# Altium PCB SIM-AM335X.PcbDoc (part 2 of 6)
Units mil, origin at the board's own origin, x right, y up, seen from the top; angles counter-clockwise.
Board outline 4041.51 x 2715.24 mil, 2 copper layers (Top Layer, Bottom Layer); 172 components, 190 nets, 855 pads, 317 vias.
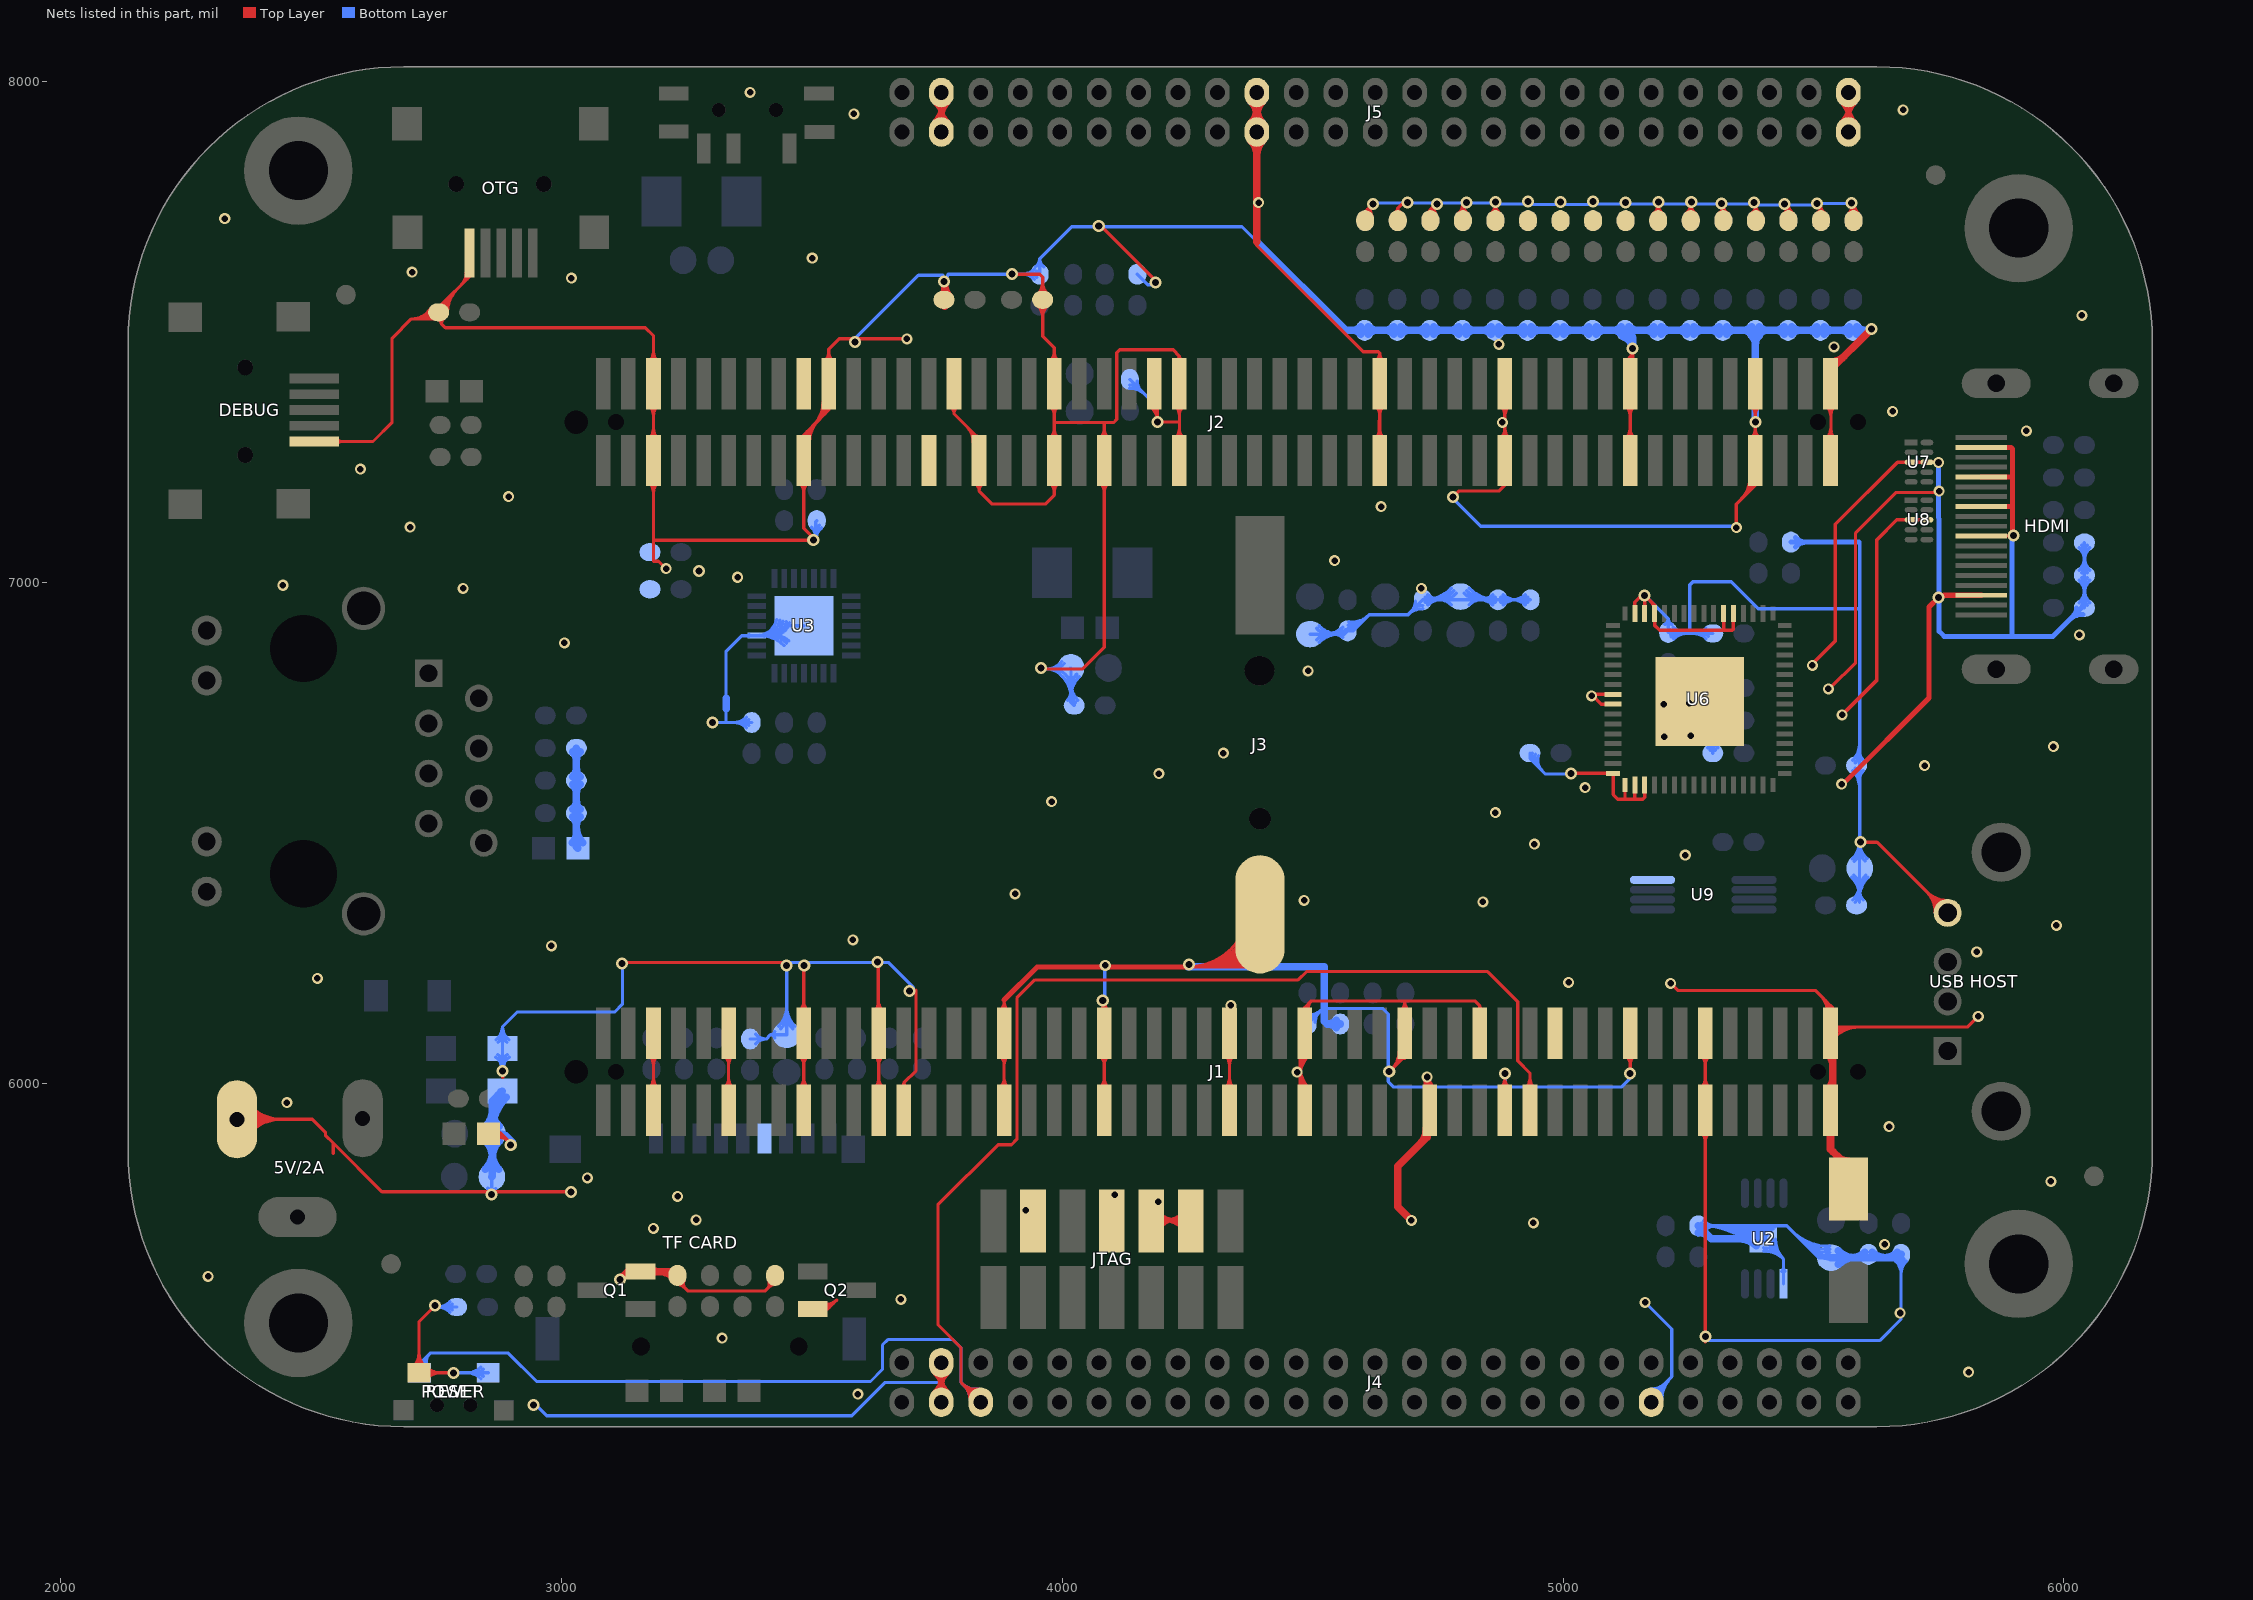
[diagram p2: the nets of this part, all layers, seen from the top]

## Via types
v1: diameter 24, hole 14, Top Layer to Bottom Layer, tented both sides, 206 vias
v2: diameter 22, hole 13, Top Layer to Bottom Layer, tented both sides, 109 vias
v3: diameter 22, hole 14, Top Layer to Bottom Layer, tented both sides, 2 vias

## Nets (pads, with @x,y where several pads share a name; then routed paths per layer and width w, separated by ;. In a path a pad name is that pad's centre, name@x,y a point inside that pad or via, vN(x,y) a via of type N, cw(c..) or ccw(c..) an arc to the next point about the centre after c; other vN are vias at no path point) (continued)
DGND: 5V/2A.3 "TF CARD.6" "USB HOST.4" C1.2 C2.2 C3.2 C4.1 C22.1 C23.2 C24.2 C25.2 C27.2 C28.2 C29.2 C30.1 C31.2 C32.2 C33.2 C34.2 C52.1 C53.2 C54.1 C55.1 C56.2 C57.2 C58.2 C59.2 C60.2 C61.2 C62.2 C63.2 C64.2 C65.2 C66.2 C67.2 C68.2 C69.2 C70.2 C71.2 C72.2 C73.2 C74.2 C75.2 C76.2 C77.2 C78.2 C79.2 C80.2 C81.2 C82.1 C83.2 CE1.2 CE2.2 CE3.2 DEBUG.5 ESD1.2 ESD2.2 ESD3.2 ESD4.2 ESD5.2 HDMI.2 HDMI.5 HDMI.8 HDMI.11 HDMI.17 J1.5 J1.6 J1.11 J1.12 J1.17 J1.18 J1.23 J1.24 J1.25 J1.33 J1.34 J1.41 J1.42 J1.51 J1.52 J1.57 J1.58 J1.66 J1.67 J1.72 J1.73 J1.84 J1.89 J1.90 J1.99 J1.100 J2.5 J2.6 J2.17 J2.20 J2.27 J2.30 J2.31 J2.37 J2.38 J2.41 J2.46 J2.47 J2.48 J2.63 J2.64 J2.73 J2.74 J2.83 J2.84 J2.93 J2.94 J2.99 J2.100 J3.2 J4.3 J4.4 J4.39 J5.3 J5.4 J5.19 J5.20 J5.49 J5.50 JTAG.4 JTAG.8 JTAG.10 JTAG.12 L1.2 LED4.2 OTG.5 POWER.2 Q1.2 Q2.2 R23.1 R24.1 R25.2 R26.2 R27.2 R28.2 R29.2 R30.2 R31.2 R32.2 R33.2 R34.2 R35.2 R36.2 R37.2 R38.2 R39.2 R40.2 R43.2 R54.2 R57.1 R59.2 R74.1 R93.1 R94.1 R96.2 RESET.2 U2.1 U2.9 U3.3 U3.29 U6.8 U6.9 U6.16 U6.17 U6.18 U6.19 U6.53 U6.54 U6.61 U6.62 U6.63 U6.65 U7.3 U7.8 U8.3 U8.8 U9.4 | length 48401.6
  Top Layer w6.5: 5V/2A.3@2352.47,5928.79 2352.47,5929 2503,5929 2529,5903 2529,5896.9 2544.45,5881.45 ; 5V/2A.3@2364.67,5916.59 cw(c2394.62,5886.64) 2394.62,5929 ; 5V/2A.3@2364.67,5940.99 ccw(c2393.61,5969.93) 2393.61,5929 ; 5V/2A.3@2369.26,5912 cw(c2410.31,5870.95) 2410.31,5929 ; 5V/2A.3@2369.26,5945.58 ccw(c2409.3,5985.62) 2409.3,5929 ; 5V/2A.3@2373.86,5907.4 cw(c2426.01,5855.25) 2426.01,5929 ; 5V/2A.3@2373.86,5950.18 ccw(c2424.99,6001.31) 2424.99,5929 ; 5V/2A.3@2378.46,5902.8 cw(c2441.7,5839.56) 2441.7,5929 ; 5V/2A.3@2378.46,5954.78 ccw(c2440.69,6017.01) 2440.69,5929 ; DEBUG.5@2506.69,7282.01 2624,7282.01 2662,7320.01 2662,7488 2700.73,7526.73 ; 2544.45,5860.55 2544.45,5881.45 ; DEBUG.5@2550.72,7277.35 cw(c2561.97,7266.09) 2561.97,7282.01 cw(c2561.97,7297.92) DEBUG.5@2550.72,7286.67 ; POWER.2@2704.38,5434.12 ccw(c2676.32,5462.18) 2716,5462.18 ccw(c2755.68,5462.18) POWER.2@2727.62,5434.12 ; POWER.2@2708.97,5429.53 ccw(c2692.01,5446.49) 2716,5446.49 ccw(c2739.99,5446.49) POWER.2@2723.03,5429.53 ; 2712.63,7526.73 ccw(c2712.63,7565.26) ESD1.2@2745.06,7544.46 ; 2724.52,7526.73 ccw(c2724.52,7557.63) ESD1.2@2750.53,7540.95 ; POWER.2@2725.98,5415.47 cw(c2742.94,5398.51) 2742.94,5422.5 cw(c2742.94,5446.49) POWER.2@2725.98,5429.53 ; POWER.2@2730.57,5410.88 cw(c2758.63,5382.82) 2758.63,5422.5 cw(c2758.63,5462.18) POWER.2@2730.57,5434.12 ; 2736.41,7526.73 ccw(c2736.41,7550) ESD1.2@2756,7537.43 ; ESD1.2@2739.59,7547.97 cw(c2700.73,7572.89) 2700.73,7526.73 ; v1(2748,5557) 2716,5525 POWER.2@2716,5422.5 v1(2785,5422.5) ; ESD1.2@2753.8,7525.86 cw(c2751.13,7516.86) 2760.51,7516.86 cw(c2773.75,7516.86) ESD1.2@2766.3,7527.81 ; ESD1.2@2759.75,7540 cw(c2794.12,7540) 2769.82,7564.31 ; ESD1.2@2766.25,7540 cw(c2816.32,7540) 2780.91,7575.4 ; ESD1.2@2772.75,7540 cw(c2838.51,7540) 2792.01,7586.5 ; 2800.49,7594.97 ccw(c2776.51,7618.95) OTG.5@2810.42,7618.95 ; 2811.58,7606.07 ccw(c2798.71,7618.95) OTG.5@2816.92,7618.95 ; OTG.5@2817.01,7658.32 2817.01,7611.5 2760.51,7555 ESD1.2@2760.51,7526.73 ; LED4.2@2853.57,5906.6 cw(c2860,5876.59) 2881.71,5898.29 ; LED4.2@2854.49,5900 2880,5900 ; LED4.2@2854.94,5900.24 cw(c2862.99,5862.67) 2890.16,5889.84 ; LED4.2@2856.3,5893.89 cw(c2865.97,5848.75) v1@2898.61,5881.39 ; LED4.2@2873.6,5895.07 cw(c2880,5893.38) 2880,5900 ; LED4.2@2873.6,5904.93 ccw(c2880,5906.62) 2880,5900 ; 2883,6012 v1(2883,6025) ; v1@2903,5877 2880,5900 ; v1(3019,5784) 2641.9,5784 2544.45,5881.45 ; v1@3130,6242 3450,6242.25 v1@3452,6242.25 ; J1.5@3176,5991.62 ccw(c3156.68,6010.94) 3184,6010.94 ccw(c3211.32,6010.94) J1.5@3192,5991.62 ; J1.6@3176,6055.93 cw(c3156.68,6036.61) 3184,6036.61 cw(c3211.32,6036.61) J1.6@3192,6055.93 ; J2.5@3176,7199.38 cw(c3156.68,7180.06) 3184,7180.06 cw(c3211.32,7180.06) J2.5@3192,7199.38 ; J2.5@3176,7288.62 ccw(c3156.68,7307.94) 3184,7307.94 ccw(c3211.32,7307.94) J2.5@3192,7288.62 ; J2.6@3176,7352.93 cw(c3156.68,7333.61) 3184,7333.61 cw(c3211.32,7333.61) J2.6@3192,7352.93 ; J2.6@3176,7442.16 ccw(c3156.68,7461.48) 3184,7461.48 ccw(c3211.32,7461.48) J2.6@3192,7442.16 ; J1.5@3184,5947 J1.6@3184,6100.54 ; v2(3209,7028) 3194,7043 3184,7043 3184,7085 ; R23.1@3231.8,5599.25 cw(c3231.8,5582.48) 3243.66,5594.34 ; R23.1@3231.8,5617 3231.8,5606.2 3252,5586 3407,5586 3426.8,5605.8 R24.1@3426.8,5617 ; R23.1@3239.24,5610.42 ccw(c3250.32,5605.08) 3241.62,5596.38 ; R23.1@3245.09,5607.6 ccw(c3259.06,5600.87) 3248.1,5589.9 ; J1.11@3326,5991.62 ccw(c3306.68,6010.94) 3334,6010.94 ccw(c3361.32,6010.94) J1.11@3342,5991.62 ; J1.12@3326,6055.93 cw(c3306.68,6036.61) 3334,6036.61 cw(c3361.32,6036.61) J1.12@3342,6055.93 ; J1.11@3334,5947 J1.12@3334,6100.54 ; 3411.1,5590.1 ccw(c3400.77,5600.43) R24.1@3413.72,5607.18 ; 3415.62,5594.62 cw(c3426.8,5583.43) R24.1@3426.8,5599.25 ; 3417.36,5596.36 ccw(c3409,5604.72) R24.1@3419.49,5610.19 ; J1.17@3476,5991.62 ccw(c3456.68,6010.94) 3484,6010.94 ccw(c3511.32,6010.94) J1.17@3492,5991.62 ; J1.18@3476,6055.93 cw(c3456.68,6036.61) 3484,6036.61 cw(c3511.32,6036.61) J1.18@3492,6055.93 ; J1.18@3476,6145.16 ccw(c3456.68,6164.48) 3484,6164.48 ccw(c3511.32,6164.48) J1.18@3492,6145.16 ; J2.17@3476,7199.38 cw(c3456.68,7180.06) 3484,7180.06 cw(c3511.32,7180.06) J2.17@3492,7199.38 ; J2.17@3482.32,7280.61 cw(c3512.98,7280.61) 3491.3,7302.3 ; J1.17@3484,5947 J1.18@3484,6100.54 v1@3484,6234 ; J2.17@3488.82,7280.61 cw(c3535.18,7280.61) 3502.4,7313.4 ; J2.17@3495.32,7280.61 cw(c3557.37,7280.61) 3513.49,7324.49 ; Q2.2@3502,5550.2 3532.2,5550.2 ; 3503.42,7314.42 ccw(c3456.9,7360.93) J2.20@3522.68,7360.93 ; 3514.51,7325.51 ccw(c3479.1,7360.93) J2.20@3529.18,7360.93 ; Q2.2@3515.6,5549.73 ccw(c3522.55,5567.4) 3535.97,5553.97 ; Q2.2@3517.98,5555.78 ccw(c3526.51,5577.46) 3542.99,5560.99 ; Q2.2@3520.35,5561.83 ccw(c3530.47,5587.53) 3550,5568 3532.2,5550.2 ; 3525.61,7336.61 ccw(c3501.29,7360.93) J2.20@3535.68,7360.93 ; J2.20@3526,7442.16 ccw(c3506.68,7461.48) 3534,7461.48 ccw(c3561.32,7461.48) J2.20@3542,7442.16 ; Q2.2@3527.83,5546.87 cw(c3532.2,5545.66) 3532.2,5550.2 ; Q2.2@3527.83,5553.52 ccw(c3532.2,5554.73) 3532.2,5550.2 ; J2.20@3530.28,7350.24 cw(c3528.45,7345) 3534,7345 ; J2.20@3537.72,7350.24 ccw(c3539.55,7345) 3534,7345 ; J1.23@3626,5991.62 ccw(c3606.68,6010.94) 3634,6010.94 ccw(c3661.32,6010.94) J1.23@3642,5991.62 ; J1.24@3626,6055.93 cw(c3606.68,6036.61) 3634,6036.61 cw(c3661.32,6036.61) J1.24@3642,6055.93 ; J1.24@3626,6145.16 ccw(c3609.09,6162.07) 3633,6162.07 ; 3633,6166.89 ccw(c3663.74,6166.89) J1.24@3642,6145.16 ; v1@3633,6243 3633,6101.54 J1.24@3634,6100.54 J1.23@3634,5947 ; J1.25@3679.08,5993.81 ccw(c3675.29,6001.65) 3684,6001.65 ; J1.25@3684,5947 3684,6001.65 ; J1.25@3688.92,5993.81 cw(c3692.71,6001.65) 3684,6001.65 ; v2(3690,7487) 3555,7487 3534,7466 J2.20@3534,7397.54 3534,7345 ; 3708.32,6186.44 3708.32,6025.96 3684,6001.65 ; J5.3@3743.07,7919.44 ccw(c3698.22,7961) J5.4@3759.33,7963.33 ; J4.3@3743.5,5384.02 ccw(c3707.05,5420.48) 3758.61,5420.48 ccw(c3810.16,5420.48) J4.3@3773.71,5384.02 ; J4.4@3743.5,5422.72 cw(c3707.05,5386.26) 3758.61,5386.26 cw(c3810.16,5386.26) J4.4@3773.71,5422.72 ; J5.4@3744.22,7958.15 cw(c3708.75,7919.87) J5.3@3760.91,7921.85 ; J5.3@3747.84,7915.02 ccw(c3714.5,7945.92) 3759.92,7947.65 ; J4.3@3748.1,5379.43 ccw(c3722.74,5404.79) 3758.61,5404.79 ccw(c3794.47,5404.79) J4.3@3769.11,5379.43 ; J4.4@3748.1,5427.31 cw(c3722.74,5401.95) 3758.61,5401.95 cw(c3794.47,5401.95) J4.4@3769.11,5427.31 ; J5.4@3748.64,7962.92 cw(c3723.83,7936.14) 3760.31,7937.53 ; J5.3@3752.61,7910.6 ccw(c3730.77,7930.83) 3760.52,7931.97 ; J4.3@3758.61,5364 J4.4@3758.61,5442.74 ; J5.4@3758.74,7978.74 J5.3@3761.74,7900 ; J5.4@3759.84,7949.77 ccw(c3801.78,7951.37) J5.3@3773.26,7920.59 ; 3760.28,7938.44 cw(c3795.48,7939.78) J5.4@3769.64,7963.72 ; 3760.44,7934.09 ccw(c3786.69,7935.09) J5.3@3768.84,7915.82 ; J5.3@3760.87,7922.76 cw(c3811.76,7924.7) J5.4@3774.41,7959.3 ; J2.30@3776.82,7352.18 cw(c3764.36,7337) 3784,7337 ; J2.30@3784,7397.54 3784,7337 ; J2.30@3791.18,7352.18 ccw(c3803.64,7337) 3784,7337 ; 3810.17,7310.83 cw(c3779.95,7280.61) J2.31@3822.68,7280.61 ; 3821.26,7299.74 cw(c3802.14,7280.61) J2.31@3829.18,7280.61 ; 3825.58,7295.42 ccw(c3834,7303.84) J2.31@3834,7291.93 ; J2.31@3826.69,7198.74 cw(c3813.39,7183) 3834,7183 ; J2.31@3841.31,7198.74 ccw(c3854.61,7183) 3834,7183 ; J1.33@3876,5991.62 ccw(c3856.68,6010.94) 3884,6010.94 ccw(c3911.32,6010.94) J1.33@3892,5991.62 ; J1.34@3876,6055.93 cw(c3856.68,6036.61) 3884,6036.61 cw(c3911.32,6036.61) J1.34@3892,6055.93 ; J1.34@3876,6145.16 ccw(c3856.68,6164.48) 3884,6164.48 ccw(c3911.32,6164.48) J1.34@3892,6145.16 ; J1.33@3884,5947 J1.34@3884,6100.54 3884,6167 ; v1(3900,7616) 3955,7616 3961,7610 ESD2.2@3961,7565 3961,7492 3984,7469 J2.38@3984,7397.54 3984,7320 ; ESD2.2@3950.57,7554.57 cw(c3925.39,7529.39) 3961,7529.39 cw(c3996.61,7529.39) ESD2.2@3971.43,7554.57 ; ESD2.2@3950.57,7575.43 ccw(c3925.39,7600.61) 3961,7600.61 ccw(c3996.61,7600.61) ESD2.2@3971.43,7575.43 ; ESD2.2@3955.17,7559.17 cw(c3941.08,7545.08) 3961,7545.08 cw(c3980.92,7545.08) ESD2.2@3966.83,7559.17 ; ESD2.2@3955.17,7570.83 ccw(c3941.08,7584.92) 3961,7584.92 ccw(c3980.92,7584.92) ESD2.2@3966.83,7570.83 ; v1@3969,6828 4041,6828 4084,6871 J2.41@4084,7244 4084,7318 4082,7320 ; J2.37@3976,7199.38 cw(c3956.68,7180.06) 3984,7180.06 cw(c4011.32,7180.06) J2.37@3992,7199.38 ; J2.37@3976,7288.62 ccw(c3956.68,7307.94) 3984,7307.94 ccw(c4011.32,7307.94) J2.37@3992,7288.62 ; J2.38@3976,7352.93 cw(c3956.68,7333.61) 3984,7333.61 cw(c4011.32,7333.61) J2.38@3992,7352.93 ; J2.38@3976,7442.16 ccw(c3956.68,7461.48) 3984,7461.48 ccw(c4011.32,7461.48) J2.38@3992,7442.16 ; J1.41@4076,5991.62 ccw(c4056.68,6010.94) 4084,6010.94 ccw(c4111.32,6010.94) J1.41@4092,5991.62 ; J1.42@4076,6055.93 cw(c4056.68,6036.61) 4084,6036.61 cw(c4111.32,6036.61) J1.42@4092,6055.93 ; J2.41@4076,7199.38 cw(c4056.68,7180.06) 4084,7180.06 cw(c4111.32,7180.06) J2.41@4092,7199.38 ; J2.41@4076,7288.62 ccw(c4056.68,7307.94) 4084,7307.94 ccw(c4111.32,7307.94) J2.41@4092,7288.62 ; J1.42@4076.17,6145.33 ccw(c4056.39,6166) 4085,6166 4085,6101.54 J1.42@4084,6100.54 J1.41@4084,5947 ; v1@4081,7709 4188,7602 v1@4188,7595 ; v1@4085,6162.07 ccw(c4108.91,6162.07) J1.42@4092,6145.16 ; J2.46@4176.36,7352.58 cw(c4146.98,7320.48) v1@4190.5,7320.48 ; J2.46@4180.75,7357.38 cw(c4160.49,7335.23) 4190.5,7335.23 ; J2.46@4184,7397.54 4190.5,7391.04 v1(4190.5,7321) 4190.73,7320.77 4234,7320.77 ; JTAG.10@4189,5728 4189.14,5727.86 4228.7,5727.86 ; JTAG.10@4189.2,5737.2 ccw(c4211.76,5759.76) 4211.76,5727.86 ; JTAG.10@4190.32,5716.04 cw(c4215.08,5696) 4215.08,5727.86 ; JTAG.10@4193.8,5741.8 ccw(c4227.45,5775.45) 4227.45,5727.86 ; JTAG.10@4195.37,5711.95 cw(c4228.7,5684.99) 4228.7,5727.86 ; JTAG.10@4197.94,5727.86 cw(c4197.94,5667.09) JTAG.12@4240.9,5710.06 ; 4207.6,5727.86 ccw(c4207.6,5774.96) JTAG.12@4240.9,5741.66 ; 4213.63,5727.86 cw(c4213.63,5682.79) JTAG.12@4245.5,5714.66 ; 4223.29,5727.86 ccw(c4223.29,5759.27) JTAG.12@4245.5,5737.06 ; J2.47@4226,7288.62 ccw(c4206.68,7307.94) 4234,7307.94 ccw(c4261.32,7307.94) J2.47@4242,7288.62 ; J2.48@4226,7352.93 cw(c4206.68,7333.61) 4234,7333.61 cw(c4261.32,7333.61) J2.48@4242,7352.93 ; J2.48@4228.87,7444.24 ccw(c4224.61,7452.61) 4234,7452.61 ; 4229.32,5727.86 cw(c4229.32,5698.48) JTAG.12@4250.1,5719.25 ; J2.47@4234,7244 4234,7320.77 ; JTAG.12@4234.58,5722.75 ccw(c4228.7,5721.92) 4228.7,5727.86 ; JTAG.12@4235.46,5732.76 cw(c4228.7,5734.96) 4228.7,5727.86 ; J2.48@4239.13,7444.24 cw(c4243.39,7452.61) 4234,7452.61 ; v1@4262.44,6233 ccw(c4262.44,6347.77) J3.2@4361.08,6289.11 ; 4273.86,6233 ccw(c4273.86,6340.98) J3.2@4366.67,6285.79 ; 4285.29,6233 ccw(c4285.29,6334.18) J3.2@4372.26,6282.46 ; 4296.72,6233 ccw(c4296.72,6327.38) J3.2@4377.84,6279.14 ; 4308.15,6233 ccw(c4308.15,6320.59) J3.2@4383.43,6275.82 ; 4319.58,6233 ccw(c4319.58,6313.79) J3.2@4389.02,6272.5 ; J1.51@4326,5991.62 ccw(c4306.68,6010.94) 4334,6010.94 ccw(c4361.32,6010.94) J1.51@4342,5991.62 ; J1.52@4326,6055.93 cw(c4306.68,6036.61) 4334,6036.61 cw(c4361.32,6036.61) J1.52@4342,6055.93 ; 4331,6233 ccw(c4331,6306.99) J3.2@4394.6,6269.17 ; J1.51@4334,5947 J1.52@4334,6100.54 ; 4342.43,6233 ccw(c4342.43,6300.2) J3.2@4400.19,6265.85 ; 4353.86,6233 ccw(c4353.86,6293.4) J3.2@4405.78,6262.53 ; J3.2@4355.5,6292.43 cw(c4251.01,6354.57) 4251.01,6233 4395,6233 J3.2@4395,6337.83 ; 4388.66,7681.34 4388.66,7673.34 4601,7461 4631.27,7461 4634,7458.27 ; J1.57@4475,5946.75 4475,6100.3 4484,6152 4497,6165 ; 4475,6001.27 ccw(c4501.66,6001.27) J1.57@4482.81,5982.42 ; v2@4475,6014.89 cw(c4533.04,6014.89) J1.58@4492,6055.93 ; v2@4475,6016.97 ccw(c4517.35,6016.97) J1.57@4487.41,5987.02 ; v2@4475,6030.58 cw(c4517.35,6030.58) J1.58@4487.41,6060.52 ; 4475,6032.66 ccw(c4533.04,6032.66) J1.57@4492,5991.62 ; 4475,6046.27 cw(c4501.66,6046.27) J1.58@4482.81,6065.12 ; J1.58@4482.53,6136.34 cw(c4494.6,6143.06) 4484.83,6152.83 ; J1.58@4488.21,6139.5 cw(c4502.41,6147.42) 4490.91,6158.91 ; J1.58@4493.89,6142.67 cw(c4510.23,6151.77) 4497,6165 ; C58.2@4605,7723 4605,7741 4622,7758 ccw(c4637.27,7742.73) C58.2@4618.1,7732.79 ; C58.2@4606.55,7726.81 cw(c4620.73,7734.15) 4609.44,7745.44 ; C58.2@4612.32,7729.8 cw(c4629,7738.44) v1@4615.72,7751.72 ; J2.64@4626,7352.93 cw(c4606.68,7333.61) 4634,7333.61 cw(c4661.32,7333.61) J2.64@4642,7352.93 ; J2.64@4626.77,7442.86 ccw(c4613.97,7458.27) 4634,7458.27 ; 4633,7305.52 cw(c4609.09,7305.52) 4626,7288.62 ccw(c4606.68,7307.94) 4634,7307.94 ccw(c4661.32,7307.94) 4642,7288.62 cw(c4663.74,7310.35) 4633,7310.35 ; 4633,7324 4633,7215 J2.63@4634,7214 ; J2.63@4634,7244 J2.64@4634,7397.54 4634,7458.27 ; J2.64@4641.23,7442.86 cw(c4654.03,7458.27) 4634,7458.27 ; v1@4657,6024 v1(4653,6024) J1.66@4684,6055 ; v1@4658.37,6029.37 ccw(c4623.8,6063.93) J1.66@4672.68,6063.93 ; C59.2@4664.4,7739.65 ccw(c4660.97,7748) 4670,7748 ; 4669.46,6040.46 ccw(c4646,6063.93) J1.66@4679.18,6063.93 ; C59.2@4670,7723 4670,7748 ; C59.2@4675.6,7739.65 cw(c4679.03,7748) 4670,7748 ; J1.66@4676.1,6145.26 ccw(c4657.83,6164) 4684,6164 ; v1@4680,7758 4670,7748 ; J1.66@4683.76,6050 4683,6050 4684,6051 J1.66@4684,6055 ; J1.66@4691.9,6145.26 cw(c4710.17,6164) 4684,6164 ; C60.2@4731.34,7740.29 ccw(c4730.14,7745) 4735,7745 ; C60.2@4735,7723 4735,7745 ; C60.2@4736.38,7727.08 cw(c4748.6,7736.65) 4737.62,7747.62 ; C60.2@4738.66,7740.29 cw(c4739.86,7745) 4735,7745 ; C60.2@4741.49,7731.09 cw(c4754.41,7741.21) v1@4742.81,7752.81 ; C60.2@4746.61,7735.09 cw(c4760.23,7745.76) 4748,7758 4735,7745 ; v1(4780,7171) 4792,7183 4872,7183 4884,7195 J2.73@4884,7244 ; C61.2@4790.99,7737.68 ccw(c4776.87,7756) v1@4800,7756 ; C61.2@4800,7723 v1@4800,7756 ; C61.2@4809.01,7737.68 cw(c4823.13,7756) v1@4800,7756 ; J1.72@4829.18,6147.4 ccw(c4825.6,6155) 4834,6155 ; J1.72@4834,6100.54 4834,6155 ; J1.72@4838.82,6147.4 cw(c4842.4,6155) 4834,6155 ; C62.2@4855.99,7737.68 ccw(c4841.87,7756) v1@4865,7756 ; C62.2@4865,7723 v1@4865,7756 ; C62.2@4874.01,7737.68 cw(c4888.13,7756) v1@4865,7756 ; J1.73@4876,5991.62 ccw(c4856.68,6010.94) 4884,6010.94 ccw(c4911.32,6010.94) J1.73@4892,5991.62 ; J1.73@4884,5947 v1(4884,6020) ; v1@5016,6619.61 U6.16@5100,6619.61 5100,6577 5109.3,6567.7 5142.31,6567.7 ; v2@5056.93,6777.07 5076.54,6757.46 U6.9@5100,6757.46 ; v2@5057,6777.15 U6.8@5100,6777.15 ; 5123.62,6569.78 U6.17@5123.62,6595.99 ; J1.84@5126,6055.93 cw(c5106.68,6036.61) 5134,6036.61 cw(c5161.32,6036.61) J1.84@5142,6055.93 ; v1(5134,6020) J1.84@5134,6100.54 ; U6.18@5143.31,6595.99 5143.31,6568.7 5142.31,6567.7 ; U6.19@5163,6595.99 5163,6571.77 5158.93,6567.7 5142.31,6567.7 ; C67.2@5181.31,7737.92 ccw(c5168.87,7755) v1@5190,7755 ; C67.2@5190,7723 v1@5190,7755 ; v1@5191,7756 v1@5190,7755 ; C67.2@5198.69,7737.92 cw(c5211.13,7755) v1@5190,7755 ; v2(5215,6200) 5229,6186 5504,6186 5539,6151 J1.100@5539,6113.13 ; C68.2@5245.99,7737.68 ccw(c5231.87,7756) v1@5255,7756 ; C68.2@5255,7723 v1@5255,7756 ; C68.2@5264.01,7737.68 cw(c5278.13,7756) v1@5255,7756 ; J1.89@5276,5902.38 cw(c5256.68,5883.06) 5284,5883.06 cw(c5311.32,5883.06) J1.89@5292,5902.38 ; J1.89@5276,5991.62 ccw(c5256.68,6010.94) 5284,6010.94 ccw(c5311.32,6010.94) J1.89@5292,5991.62 ; J1.90@5276,6055.93 cw(c5256.68,6036.61) 5284,6036.61 cw(c5311.32,6036.61) J1.90@5292,6055.93 ; v1@5284,5484 J1.89@5284,5944 ; J1.89@5284,5947 J1.90@5284,6100.54 ; C69.2@5312.03,7738.41 ccw(c5302.66,7753) v1@5320,7753 ; v1(5316,7757) v1@5320,7753 ; C69.2@5320,7723 v1@5320,7753 ; C69.2@5327.97,7738.41 cw(c5337.34,7753) v1@5320,7753 ; J2.93@5376,7288.62 ccw(c5356.68,7307.94) 5384,7307.94 ccw(c5411.32,7307.94) J2.93@5392,7288.62 ; J2.94@5376,7352.93 cw(c5356.68,7333.61) 5384,7333.61 cw(c5411.32,7333.61) J2.94@5392,7352.93 ; C70.2@5377.03,7738.41 ccw(c5367.66,7753) v1@5385,7753 ; v1@5381,7757 v1@5385,7753 ; J2.93@5384,7244 J2.94@5384,7397.54 ; C70.2@5385,7723 v1@5385,7753 ; C70.2@5392.97,7738.41 cw(c5402.34,7753) v1@5385,7753 ; C71.2@5440.99,7737.68 ccw(c5426.87,7756) v1@5450,7756 ; C71.2@5450,7723 v1@5450,7756 ; C71.2@5459.01,7737.68 cw(c5473.13,7756) v1@5450,7756 ; C72.2@5508.34,7739.16 ccw(c5502.85,7750) v1@5515,7750 ; 5512.45,6177.55 cw(c5472.07,6137.16) J1.100@5529.18,6137.16 ; C72.2@5515,7723 v1@5515,7750 ; C72.2@5521.66,7739.16 cw(c5527.15,7750) v1@5515,7750 ; 5523.55,6166.45 cw(c5494.26,6137.16) J1.100@5535.68,6137.16 ; J1.99@5526,5902.38 cw(c5494.61,5870.99) 5539,5870.99 ; J1.99@5526,5991.62 ccw(c5494.61,6023.01) 5539,6023.01 ; J1.100@5526,6055.93 cw(c5494.61,6024.54) 5539,6024.54 ; J2.99@5526,7288.62 ccw(c5504.26,7310.35) 5535,7310.35 ; J2.100@5526,7352.93 cw(c5504.26,7331.19) 5535,7331.19 ; J1.100@5528.21,6106.33 cw(c5544.63,6089.91) J1.100@5544.63,6113.13 ; J1.99@5530.59,5906.98 cw(c5510.3,5886.69) 5539,5886.69 ; J1.99@5530.59,5987.02 ccw(c5510.3,6007.31) 5539,6007.31 ; J1.100@5530.59,6060.52 cw(c5510.3,6040.23) 5539,6040.23 ; J1.100@5532.81,6101.73 cw(c5560.32,6074.22) 5560.32,6113.13 ; J2.100@5534,7397.54 5534,7397 5535,7397 J2.99@5535,7200 ; 5534.65,6155.35 cw(c5516.45,6137.16) J1.100@5542.18,6137.16 ; v2@5534.94,6790.94 5584,6840 5584,7099.56 5664.53,7180.09 5748.27,7180.09 v2(5750.93,7182.75) ; 5535,7305.52 ccw(c5558.91,7305.52) J2.99@5542,7288.62 ; 5535,7336.02 cw(c5558.91,7336.02) J2.100@5542,7352.93 ; J1.100@5537.41,6097.14 cw(c5576.01,6058.53) 5576.01,6113.13 ; 5539,5864 J1.99@5539,5947 ; 5539,5895.14 cw(c5549.25,5895.14) J1.99@5542,5902.38 ; J1.99@5539,5952 J1.100@5539,6113.13 ; 5539,5998.86 ccw(c5549.25,5998.86) J1.99@5542,5991.62 ; 5539,6048.68 cw(c5549.25,6048.68) J1.100@5542,6055.93 ; J1.100@5542,6092.54 cw(c5591.71,6042.84) 5591.71,6113.13 ; J5.49@5554.66,7920.02 ccw(c5518.21,7956.48) 5569.76,7956.48 ccw(c5621.32,7956.48) J5.49@5584.87,7920.02 ; J5.50@5554.66,7958.72 cw(c5518.21,7922.26) 5569.76,7922.26 cw(c5621.32,7922.26) J5.50@5584.87,7958.72 ; J5.49@5559.26,7915.43 ccw(c5533.9,7940.79) 5569.76,7940.79 ccw(c5605.63,7940.79) J5.49@5580.27,7915.43 ; J5.50@5559.26,7963.31 cw(c5533.9,7937.95) 5569.76,7937.95 cw(c5605.63,7937.95) J5.50@5580.27,7963.31 ; C73.2@5569.57,7736.43 ccw(c5544.39,7761.61) 5580,7761.61 ccw(c5615.61,7761.61) C73.2@5590.43,7736.43 ; J5.49@5569.76,7900 J5.50@5569.76,7978.74 ; C73.2@5574.17,7731.83 ccw(c5560.08,7745.92) 5580,7745.92 ccw(c5599.92,7745.92) C73.2@5585.83,7731.83 ; C73.2@5580,7723 v1@5580,7763 ; v1(5594,6482) 5627,6482 5768,6341 ; 5743.3,6341 ccw(c5683.66,6341) 5725.83,6383.17 ccw(c5768,6425.34) 5768,6365.7 ; 5749.8,6341 ccw(c5705.85,6341) 5736.93,6372.07 ccw(c5768,6403.15) 5768,6359.2 ; 5756.3,6341 ccw(c5728.04,6341) 5748.02,6360.98 ccw(c5768,6380.96) 5768,6352.7 ; v2(5829,6134.13) 5808,6113.13 J1.100@5539,6113.13 ; HDMI.11@5835,7093.15 v1@5896.15,7093.15 ; 2700.73,7526.73 ESD1.2@2760.51,7526.73 ; ESD1.2@2760.51,7526.73 2760.51,7517 2768.51,7509 3168,7509 3184,7493 J2.6@3184,7397.54 J2.5@3184,7244 3184,7085 ; 3184,7085 3508,7085 3484,7109 J2.17@3484,7244 3484,7295 3534,7345 ; 3784,7337 3834,7287 J2.31@3834,7244 3834,7183 ; 3834,7183 3860,7157 3966,7157 3984,7175 J2.37@3984,7244 3984,7320 ; 3984,7320 4082,7320 ; 4082,7320 4103,7320 4109,7326 4109,7459 4115,7465 4221.62,7465 4234,7452.62 ; 4234,7320.77 J2.48@4234,7397.54 4234,7452.62 ; 4497,6165 4685,6165 ; J1.66@4684,6055 J1.66@4684,6100.54 4684,6164 ; 4684,6164 4685,6165 ; 4685,6165 4824,6165 4834,6155
  Top Layer w7: J2.73@4876.17,7288.44 ccw(c4857.28,7307.33) 4884,7307.33 ccw(c4910.72,7307.33) J2.73@4891.83,7288.44 ; J2.74@4876.17,7353.1 cw(c4857.28,7334.21) 4884,7334.21 cw(c4910.72,7334.21) J2.74@4891.83,7353.1 ; J2.73@4884,7244 J2.74@4884,7397.54 ; J2.83@5126.17,7288.44 ccw(c5107.28,7307.33) 5134,7307.33 ccw(c5160.72,7307.33) J2.83@5141.83,7288.44 ; J2.84@5126.17,7353.1 cw(c5107.28,7334.21) 5134,7334.21 cw(c5160.72,7334.21) J2.84@5141.83,7353.1 ; J2.84@5127,7442.73 ccw(c5106.4,7468) v1(5139,7468) 5139,7402.54 J2.84@5134,7397.54 J2.83@5134,7244 ; J2.84@5131.43,7437.31 ccw(c5118.42,7453.25) 5139,7453.25 ; 5139,7448.81 ccw(c5148.65,7448.81) J2.84@5141.83,7441.98 ; U6.63@5143.31,6938.62 5143.31,6961.31 5157,6975 v1(5163,6975) ; U6.62@5163,6938.62 v1(5163,6975) ; 5176.63,6961.38 cw(c5165.6,6950.35) U6.61@5181.2,6950.35 ; U6.54@5320.55,6938.62 5320.55,6905 ; U6.53@5340.24,6938.62 5340.24,6907.19 5338.05,6905 5320.55,6905 ; v2(5346,7110) 5346,7157 5384,7195 J2.93@5384,7244 ; 5356.35,7167.35 ccw(c5316.31,7207.39) J2.93@5372.93,7207.39 ; 5368.3,7179.3 ccw(c5340.21,7207.39) J2.93@5379.93,7207.39 ; 5380.25,7191.25 ccw(c5364.11,7207.39) J2.93@5386.93,7207.39 ; v2@5503,6843 5543.69,6883.69 5543.69,7116.43 5667.89,7240.63 U7.3@5695,7240.63 U7.8@5726.5,7240.63 v3@5749.63,7240.63 ; v2(5557,6736) 5626.75,6805.75 5626.75,7085.74 5666.64,7125.63 U8.3@5695,7125.63 U8.8@5726.5,7125.63 ; v1(5163,6975) 5182.7,6955.31 U6.61@5182.7,6938.62 5182.7,6915.3 5193,6905 5320.55,6905
  Top Layer w10: 3884,6167 3950,6233 v1@4251,6233 ; v2@5551.57,6599.43 5560.43,6599.43 5730.75,6769.75 5730.75,6951.75 v1(5750,6971) ; v1@5761.04,6975.04 HDMI.17@5835,6975.04 ; HDMI.8@5835,7152.2 5895.57,7152.2 5897.68,7150.09 ; HDMI.5@5835,7211.26 5895.42,7211.26 5897.68,7209 ; HDMI.2@5835,7270.32 5894.32,7270.32 5897.68,7266.95 5897.68,7209 ; v1@5896.15,7093.15 5896.15,7101.62 5897.68,7103.15 5897.68,7150.09 ; 5897.68,7150.09 5897.68,7209
  Top Layer w15: v1(3117,5609) 3132.8,5624.8 Q1.2@3158,5624.8 3224,5624.8 R23.1@3231.8,5617 ; Q1.2@3177.61,5618.97 cw(c3191.69,5604.89) 3191.69,5624.8 cw(c3191.69,5644.72) Q1.2@3177.61,5630.64 ; 3194.86,5624.8 cw(c3194.86,5583.05) R23.1@3224.38,5612.58 ; ESD3.2@3759.58,7572.42 ccw(c3744.07,7587.94) 3766,7587.94 ; ESD3.2@3766,7552 v1@3766,7601 ; v1@3766,7592.76 ccw(c3794.76,7592.76) ESD3.2@3774.42,7572.42 ; J5.19@4376.57,7882.98 cw(c4347.36,7853.78) 4388.66,7853.78 cw(c4429.96,7853.78) J5.19@4400.76,7882.98 ; J5.19@4376.57,7917.02 ccw(c4347.36,7946.22) 4388.66,7946.22 ccw(c4429.96,7946.22) J5.19@4400.76,7917.02 ; J5.20@4376.57,7961.72 cw(c4347.36,7932.52) 4388.66,7932.52 cw(c4429.96,7932.52) J5.20@4400.76,7961.72 ; 4388.66,7681.34 J5.19@4388.66,7900 J5.20@4388.66,7978.74 ; v2(4697,5727) 4670,5754 4670,5835 4728.5,5893.5 v2(4728.5,6013.18) ccw(c4762.51,6013.18) J1.67@4738.91,5988.7 ; 4713.89,5878.89 ccw(c4682.38,5910.39) J1.67@4726.93,5910.39 ; 4728.5,5892.63 cw(c4740.26,5892.63) J1.67@4736.35,5903.72 ; J1.99@5529,5905.39 cw(c5516.94,5893.32) 5534,5893.32 cw(c5551.06,5893.32) J1.99@5539,5905.39 ; J1.99@5529,5988.61 ccw(c5505.48,6012.14) 5538.75,6012.14 ; J1.100@5529,6058.93 cw(c5505.48,6035.41) 5538.75,6035.41 ; J1.100@5534,6100.54 5538.75,6095.8 5538.75,5951.75 J1.99@5534,5947 5534,5869 5539,5864 CE3.2@5570,5833 ; J2.100@5534,7397.54 5534,7425 v1@5614,7505 ; J2.100@5534,7441.23 ccw(c5534,7480.4) 5561.7,7452.7 ; 5545.78,5857.22 cw(c5520.18,5831.63) CE3.2@5554.16,5819.16 ; 5549.15,5853.85 ccw(c5570,5874.71) CE3.2@5570,5845.22
  Bottom Layer w6.5: v1(2748,5557) 2751,5554 R43.2@2791,5554 ; R43.2@2777.57,5543.57 ccw(c2752.39,5518.39) 2752.39,5554 ccw(c2752.39,5589.61) R43.2@2777.57,5564.43 ; R43.2@2782.17,5548.17 ccw(c2768.08,5534.08) 2768.08,5554 ccw(c2768.08,5573.92) R43.2@2782.17,5559.83 ; v1(2785,5422.5) RESET.2@2854,5422.5 ; RESET.2@2839.43,5410.88 ccw(c2811.37,5382.82) 2811.37,5422.5 ccw(c2811.37,5462.18) RESET.2@2839.43,5434.12 ; RESET.2@2844.02,5415.47 ccw(c2827.06,5398.51) 2827.06,5422.5 ccw(c2827.06,5446.49) RESET.2@2844.02,5429.53 ; C2.2@2852.92,5790.89 cw(c2848.21,5779) v1(2861,5779) ; C1.2@2861.1,5900.87 cw(c2875.01,5877.38) 2894.32,5896.68 ; C2.2@2861.5,5814 2861,5813.5 v1(2861,5779) ; C1.2@2862.5,5900 2891,5900 2903,5888 v1@2903,5877 ; C1.2@2864.41,5895.27 cw(c2879.42,5869.94) 2900.24,5890.76 ; C1.2@2867.72,5889.68 cw(c2883.82,5862.51) v1@2906.16,5884.84 ; CE1.2@2869.14,6052.84 cw(c2847.86,6025.5) v1@2882.5,6025.5 ; C2.2@2869.2,5790.56 ccw(c2873.25,5779) v1(2861,5779) ; CE1.2@2869.45,6087.4 ccw(c2849.88,6113.5) 2882.5,6113.5 ; CE1.2@2873.13,6057.97 cw(c2858.21,6038.8) 2882.5,6038.8 cw(c2906.79,6038.8) CE1.2@2891.87,6057.97 ; CE1.2@2873.35,6082.2 ccw(c2859.63,6100.5) 2882.5,6100.5 ccw(c2905.37,6100.5) CE1.2@2891.65,6082.2 ; v1(2883,6025) v1@2882.5,6025.5 ; CE1.2@2895.55,6087.4 cw(c2915.12,6113.5) 2882.5,6113.5 ; CE1.2@2895.86,6052.84 ccw(c2917.14,6025.5) v1@2882.5,6025.5 ; v1(2944,5358) 2950,5358 2971,5337 3580,5337 3646.46,5403.46 3758.61,5403.46 ; v1@3122,6236 3122,6158 3107,6143 2912,6143 2882.5,6113.5 ; v1(3302,6721) 3329,6721 ; 3329,6748 3329,6721 ; 3329,6769 3329,6863.37 3360,6894.37 U3.3@3390,6894.37 ; R54.2@3369.57,6710.57 ccw(c3344.39,6685.39) 3344.39,6721 ccw(c3344.39,6756.61) R54.2@3369.57,6731.43 ; R54.2@3374.17,6715.17 ccw(c3360.08,6701.08) 3360.08,6721 ccw(c3360.08,6740.92) R54.2@3374.17,6726.83 ; U3.3@3375.33,6892.49 ccw(c3370.79,6887.96) 3370.79,6894.37 ccw(c3370.79,6900.78) U3.3@3375.33,6896.25 ; C31.2@3377,6089 3409,6089 ; R54.2@3380,6721 3329,6721 ; C31.2@3388.22,6079.42 cw(c3409,6061.67) 3409,6089 ; C31.2@3388.22,6098.58 ccw(c3409,6116.33) 3409,6089 ; U3.3@3397.19,6894.37 cw(c3397.19,6826.72) U3.29@3445.03,6874.56 ; U3.3@3398.14,6894.37 ccw(c3398.14,6933.6) U3.29@3436.4,6924.92 ; U3.3@3404.67,6892.49 cw(c3409.21,6887.96) 3409.21,6894.37 cw(c3409.21,6900.78) U3.3@3404.67,6896.25 ; U3.3@3406.28,6894.37 ccw(c3406.28,6931.76) U3.29@3442.74,6923.49 ; 3412.88,6894.37 cw(c3412.88,6842.41) U3.29@3449.62,6879.15 ; 3414.42,6894.37 ccw(c3414.42,6929.91) U3.29@3449.08,6922.05 ; 3422.56,6894.37 ccw(c3422.56,6928.06) U3.29@3455.42,6920.61 ; C30.1@3426.17,6091.03 ccw(c3417.56,6088.54) 3417.5,6097.5 ; C30.1@3426.19,6104.05 cw(c3417.44,6106.63) 3417.5,6097.5 ; U3.29@3428.58,6894.37 cw(c3428.58,6858.1) U3.29@3454.22,6883.75 ; U3.29@3430.07,6926.36 cw(c3390,6935.45) U3.3@3390,6894.37 ; C30.1@3433.56,6113.94 ccw(c3393.87,6153.63) 3450,6153.63 ccw(c3506.13,6153.63) C30.1@3466.44,6113.94 ; C30.1@3438.16,6109.34 ccw(c3409.56,6137.94) 3450,6137.94 ccw(c3490.44,6137.94) C30.1@3461.84,6109.34 ; C30.1@3450,6097.5 C30.1@3450,6097.73 ; v1(3450,6236) C30.1@3450,6097.73 ; v1@3451.12,6234.88 3458.25,6242 v1@3625.75,6242 ; U3.29@3484.49,6914.02 3446.65,6914.02 3427,6894.37 U3.3@3390,6894.37 ; C24.2@3499.57,7110.57 cw(c3479.22,7090.22) v1@3508,7090.22 ; v1@3508,7084.95 cw(c3540.43,7084.95) C24.2@3519.51,7109.73 ; v1@3508,7085 3508,7122 C24.2@3510,7124 ; 3508,7098.94 cw(c3528.62,7098.94) C24.2@3515.32,7114.7 ; v1@3586,7487 3713,7614 3762,7614 ; v1@3640.25,6242 3652.76,6242 v1@3702.76,6192 ; J4.3@3749.06,5388.03 ccw(c3741.36,5403.46) 3758.61,5403.46 ; J4.3@3758.61,5364 3758.61,5403.46 ; v1@3766,7595 3772,7616 v1(3900,7616) ESD5.2@3955,7616 3955,7647 ; J4.3@3768.15,5388.03 cw(c3775.86,5403.46) 3758.61,5403.46 ; ESD5.2@3944.57,7605.57 ccw(c3919.39,7580.39) 3919.39,7616 ccw(c3919.39,7651.61) ESD5.2@3944.57,7626.43 ; ESD5.2@3946.66,7631.16 ccw(c3935.8,7647) 3955,7647 ; ESD5.2@3949.17,7610.17 ccw(c3935.08,7596.08) 3935.08,7616 ccw(c3935.08,7635.92) ESD5.2@3949.17,7621.83 ; ESD5.2@3963.34,7631.16 cw(c3974.2,7647) 3955,7647 ; 3982.28,6828 ccw(c3982.28,6855.84) C4.1@4004.27,6838.77 ; 3982.86,6828 cw(c3982.86,6799.7) C4.1@4004.62,6817.79 ; C4.1@3999.13,6842.76 cw(c3969,6866.14) v1@3969,6828 ; C4.1@3999.62,6813.64 ccw(c3969,6788.18) v1@3969,6828 ; C4.1@4017.5,6809 C4.1@4017.5,6830 4015.5,6828 v1@3969,6828 ; v1@4085,6166 4085,6227 v2@4086,6228 ; R57.1@4135,7388.25 cw(c4135,7345.4) 4165.3,7375.7 ; R57.1@4135,7394.75 cw(c4135,7367.59) 4154.2,7386.8 ; R57.1@4135,7406 4190.5,7350.5 v1(4190.5,7321) ; R57.1@4149.75,7403 ccw(c4178.12,7403) 4158.06,7382.94 ; ESD4.2@4150,7616 4171,7595 v1@4188,7595 ; 4389,7681 4359,7711 4019,7711 3955,7647 ; R74.1@4490,6119 4521,6150 4523,6150 4640,6150 4651,6139 4651,6004 4662,5993 4885,5993 ; R74.1@4490,6130.25 ccw(c4490,6157.41) 4509.2,6138.2 ; R74.1@4490,6136.75 ccw(c4490,6179.6) 4520.3,6149.3 ; R74.1@4504.75,6122 cw(c4533.12,6122) 4513.06,6142.06 ; C56.2@4570,6904 4581,6904 4613,6936 ; C56.2@4570.2,6908.74 ccw(c4573.56,6937.46) 4594.01,6917.01 ; C56.2@4570.96,6915.19 ccw(c4575.55,6954.46) 4603.51,6926.51 ; C56.2@4571.71,6921.65 ccw(c4577.54,6971.46) 4613,6936 ; v1@4622,7758 v1@4865,7758 ; 4689.7,6935.7 cw(c4720,6905.4) C57.2@4720,6948.25 ; 4696.94,6942.94 ccw(c4676.88,6963) C57.2@4705.25,6963 ; 4700.8,6946.8 cw(c4720,6927.59) C57.2@4720,6954.75 ; C57.2@4720,6966 4690,6936 4613,6936 ; v1@4865,7756 v1@4930,7756 ; v1(4884,6020) 4885,6019 4885,5993 ; v1@4930,7755 v1@5058,7755 ; C74.2@4934,6660 4934,6649 4965,6618 v1@5016,6618 ; C74.2@4938.66,6659.44 ccw(c4956.74,6653.28) 4943.23,6639.77 ; C74.2@4944.81,6657.34 ccw(c4967.76,6649.53) 4950.62,6632.38 ; C74.2@4950.96,6655.25 ccw(c4978.77,6645.77) 4958,6625 ; v1@5060,7756 5369,7756 ; v1(5134,6020) 5134,6011 5116,5993 4885,5993 ; v2(5164,5563) 5216.58,5510.42 5217,5510 5217,5415 5189,5387 5175.93,5387 J4.39@5175.93,5364 ; J4.39@5175.93,5383.78 ccw(c5175.93,5407.55) 5192.74,5390.74 ; J4.39@5175.93,5390.28 ccw(c5175.93,5429.74) 5203.84,5401.84 ; J4.39@5184.29,5368.92 cw(c5216.55,5368.92) 5193.74,5391.74 ; J4.39@5190.79,5368.92 cw(c5238.74,5368.92) 5204.83,5402.83 ; J4.39@5197.29,5368.92 cw(c5260.94,5368.92) 5215.93,5413.93 ; C79.2@5215.83,6892.17 cw(c5231.98,6876.02) 5231.98,6898.85 ; C79.2@5216,6898.85 C78.2@5299,6898.85 ; C79.2@5220.43,6887.57 cw(c5247.67,6860.33) 5247.67,6898.85 ; C79.2@5220.43,6908.43 ccw(c5243.55,6931.55) 5243.55,6898.85 ; R59.2@5270,5716 5447,5716 5510.5,5652.5 C25.2@5535,5652.5 ; R59.2@5275.83,5710.17 cw(c5289.92,5696.08) 5289.92,5716 cw(c5289.92,5735.92) R59.2@5275.83,5721.83 ; R59.2@5278.69,5716 cw(c5278.69,5568.69) U2.9@5382.85,5672.85 ; R59.2@5280.43,5705.57 cw(c5305.61,5680.39) 5305.61,5716 cw(c5305.61,5751.61) R59.2@5280.43,5726.43 ; v1@5284,5487 5632,5487 5675,5530 C22.1@5675,5659 ; C78.2@5285.57,6888.42 ccw(c5260.39,6863.24) 5260.39,6898.85 ccw(c5260.39,6934.46) C78.2@5285.57,6909.28 ; C78.2@5290.17,6893.02 ccw(c5276.08,6878.94) 5276.08,6898.85 ccw(c5276.08,6918.77) C78.2@5290.17,6904.69 ; 5294.38,5716 cw(c5294.38,5584.38) U2.9@5387.45,5677.45 ; 5310.07,5716 cw(c5310.07,5600.07) U2.9@5392.05,5682.05 ; 5325.76,5716 cw(c5325.76,5615.76) U2.9@5396.64,5686.64 ; 5336,7002 5390,6948 ; 5341.46,5716 cw(c5341.46,5631.46) U2.9@5401.24,5691.24 ; 5357.15,5716 cw(c5357.15,5647.15) U2.9@5405.83,5695.83 ; U2.9@5372.84,5716 cw(c5372.84,5662.84) U2.9@5410.43,5700.43 ; v1@5381,7754 v1@5507,7754 ; U2.9@5388.53,5716 cw(c5388.53,5678.53) U2.9@5415.03,5705.03 ; U2.9@5400,5690 5440,5650 ; U2.9@5400.44,5672.26 cw(c5401.41,5632.85) 5429.28,5660.72 cw(c5457.15,5688.59) U2.9@5417.74,5689.56 ; U2.9@5400.6,5665.76 cw(c5401.92,5611.93) 5440,5650 ; U2.9@5404.22,5716 cw(c5404.22,5694.22) U2.9@5419.62,5709.62 ; U2.9@5419.92,5716 cw(c5419.92,5709.92) U2.9@5424.22,5714.22 ; U2.9@5424.24,5689.4 ccw(c5478.07,5688.08) 5440,5650 ; U2.1@5436.73,5624.92 ccw(c5428.84,5632.82) 5440,5632.82 ccw(c5451.16,5632.82) U2.1@5443.27,5624.92 ; U2.1@5440,5600 5440,5650 ; 5458.5,5704.5 ccw(c5528.18,5774.18) C25.2@5532.49,5675.73 ; 5468.95,5694.05 ccw(c5529.06,5754.16) C25.2@5532.77,5669.23 ; 5479.39,5683.61 ccw(c5529.93,5734.14) C25.2@5533.05,5662.74 ; 5489.84,5673.16 ccw(c5530.81,5714.13) C25.2@5533.34,5656.25 ; 5500.28,5662.72 ccw(c5531.68,5694.11) C25.2@5533.62,5649.75 ; v1(5507,7757) v1@5574,7757 ; J5.49@5569.76,7900 J5.49@5580,7889.76 ; C82.1@5576.06,6412.06 cw(c5537.58,6373.58) C83.2@5592,6373.58 ; C82.1@5577.1,6448.91 ccw(c5547.83,6482) v1@5592,6482 ; C83.2@5578.57,6366.43 ccw(c5546.15,6398.85) 5592,6398.85 ; C82.1@5580.66,6416.66 cw(c5553.27,6389.27) 5592,6389.27 ; C82.1@5581.4,6444.05 ccw(c5560.59,6467.57) 5592,6467.57 ; C83.2@5583.17,6361.83 ccw(c5561.84,6383.16) 5592,6383.16 ; C83.2@5592,6362 v1@5592,6482 ; C83.2@5592,6371.16 cw(c5649.84,6371.16) C82.1@5608.94,6412.06 ; 5592,6384.37 ccw(c5617.37,6384.37) C83.2@5599.43,6366.43 ; 5592,6386.85 cw(c5634.15,6386.85) C82.1@5604.34,6416.66 ; 5592,6468.18 ccw(c5622.87,6468.18) C82.1@5603.18,6444.4 ; C82.1@5607.33,6449.41 cw(c5634.31,6482) v1@5592,6482 ; C22.1@5664.57,5645.57 cw(c5639.39,5620.39) 5675,5620.39 cw(c5710.61,5620.39) C22.1@5685.43,5645.57 ; C22.1@5669.17,5650.17 cw(c5655.08,5636.08) 5675,5636.08 cw(c5694.92,5636.08) C22.1@5680.83,5650.17 ; 5768,6341 5768,6355.17 ; v1@2882.5,6025.5 CE1.2@2882.5,6070 2882.5,6113.5 ; 3409,6089 3417.5,6097.5 ; 3417.5,6097.5 C30.1@3450,6097.73
  Bottom Layer w7: C4.1@4001.24,6812.24 cw(c3961.97,6772.97) 4017.5,6772.97 cw(c4073.03,6772.97) C4.1@4033.76,6812.24 ; C4.1@4006.19,6817.19 cw(c3978.87,6789.87) 4017.5,6789.87 cw(c4056.13,6789.87) C4.1@4028.81,6817.19 ; C3.2@4010.75,6765.25 ccw(c3994.44,6781.56) 4017.5,6781.56 ccw(c4047.56,6781.56) C3.2@4026.3,6760.3 ; 4017.5,6798.46 ccw(c4064.46,6798.46) C3.2@4031.25,6765.25 ; C4.1@4017.5,6809 4017.5,6761.5 C3.2@4024,6755 ; C54.1@4495,6897.5 4563.5,6897.5 C56.2@4570,6904 ; C54.1@4507.81,6886.19 cw(c4535.13,6858.87) 4535.13,6897.5 cw(c4535.13,6936.13) C54.1@4507.81,6908.81 ; C54.1@4512.76,6881.24 cw(c4552.03,6841.97) 4552.03,6897.5 cw(c4552.03,6953.03) C54.1@4512.76,6913.76 ; 4526.54,6897.5 ccw(c4526.54,6944.46) C56.2@4559.75,6911.25 ; C56.2@4559.75,6890.75 ccw(c4543.44,6874.44) 4543.44,6897.5 ccw(c4543.44,6927.56) C56.2@4564.7,6906.3 ; C57.2@4720,6966 C80.2@4870,6966 C81.2@4935,6966 ; C57.2@4722.28,6966 ccw(c4722.28,7043.72) C55.1@4777.24,6988.76 ; C57.2@4725.3,6960.7 cw(c4738.11,6947.89) 4738.11,6966 cw(c4738.11,6984.11) C57.2@4725.3,6971.3 ; C57.2@4730.25,6955.75 cw(c4755.01,6930.99) 4755.01,6966 cw(c4755.01,7001.01) C57.2@4730.25,6976.25 ; 4739.18,6966 ccw(c4739.18,7026.82) C55.1@4782.19,6983.81 ; 4753.67,6966 cw(c4753.67,6932.67) C55.1@4777.24,6956.24 ; 4756.08,6966 ccw(c4756.08,7009.92) C55.1@4787.14,6978.86 ; v1@4780,7175 v1(4780,7171) 4780,7169 4836,7113 v2@5344,7113 ; C55.1@4802.86,6978.86 ccw(c4833.92,7009.92) 4833.92,6966 ; C55.1@4807.81,6983.81 ccw(c4850.82,7026.82) 4850.82,6966 ; C55.1@4812.76,6956.24 cw(c4836.33,6932.67) 4836.33,6966 ; C55.1@4812.76,6988.76 ccw(c4867.72,7043.72) C80.2@4867.72,6966 ; C80.2@4859.75,6955.75 ccw(c4834.99,6930.99) 4834.99,6966 ccw(c4834.99,7001.01) C80.2@4859.75,6976.25 ; C80.2@4864.7,6960.7 ccw(c4851.89,6947.89) 4851.89,6966 ccw(c4851.89,6984.11) C80.2@4864.7,6971.3 ; C80.2@4875.3,6960.7 cw(c4888.11,6947.89) 4888.11,6966 cw(c4888.11,6984.11) C80.2@4875.3,6971.3 ; C80.2@4880.25,6955.75 cw(c4905.01,6930.99) 4905.01,6966 cw(c4905.01,7001.01) C80.2@4880.25,6976.25 ; C81.2@4924.75,6955.75 ccw(c4899.99,6930.99) 4899.99,6966 ccw(c4899.99,7001.01) C81.2@4924.75,6976.25 ; C81.2@4929.7,6960.7 ccw(c4916.89,6947.89) 4916.89,6966 ccw(c4916.89,6984.11) C81.2@4929.7,6971.3 ; v1(5163,6975) 5210,6928.01 ; C79.2@5203.25,6916.83 ccw(c5197.38,6928.01) 5210,6928.01 ; C79.2@5215.3,6895.7 cw(c5228.11,6882.89) 5228.11,6901 cw(c5228.11,6919.11) C79.2@5215.3,6906.3 ; C79.2@5216.75,6916.83 cw(c5222.62,6928.01) 5210,6928.01 ; C79.2@5220.25,6890.75 cw(c5245.01,6865.99) 5245.01,6901 cw(c5245.01,6936.01) C79.2@5220.25,6911.25 ; C75.2@5288.75,6670.25 ccw(c5263.99,6695.01) 5299,6695.01 ccw(c5334.01,6695.01) C75.2@5309.25,6670.25 ; C76.2@5288.75,6714.75 cw(c5263.99,6689.99) 5299,6689.99 cw(c5334.01,6689.99) C76.2@5309.25,6714.75 ; C76.2@5288.75,6735.25 ccw(c5263.99,6760.01) 5299,6760.01 ccw(c5334.01,6760.01) C76.2@5309.25,6735.25 ; C77.2@5288.75,6779.75 cw(c5263.99,6754.99) 5299,6754.99 cw(c5334.01,6754.99) C77.2@5309.25,6779.75 ; C75.2@5293.7,6665.3 ccw(c5280.89,6678.11) 5299,6678.11 ccw(c5317.11,6678.11) C75.2@5304.3,6665.3 ; C76.2@5293.7,6719.7 cw(c5280.89,6706.89) 5299,6706.89 cw(c5317.11,6706.89) C76.2@5304.3,6719.7 ; C76.2@5293.7,6730.3 ccw(c5280.89,6743.11) 5299,6743.11 ccw(c5317.11,6743.11) C76.2@5304.3,6730.3 ; C77.2@5293.7,6784.7 cw(c5280.89,6771.89) 5299,6771.89 cw(c5317.11,6771.89) C77.2@5304.3,6784.7 ; C75.2@5299,6660 C76.2@5299,6725 C77.2@5299,6790 ; 5336,7002 5259.43,7002 5253.43,6996 5253.43,6901 C79.2@5210,6901 5210,6928.01 ; 5390,6948 5590,6948 5592,6946 ; R94.1@5578.75,6624.75 cw(c5546.75,6592.75) 5592,6592.75 ; R94.1@5578.75,6645.25 ccw(c5546.75,6677.25) 5592,6677.25 ; R94.1@5583.7,6629.7 cw(c5563.65,6609.65) 5592,6609.65 ; R94.1@5583.7,6640.3 ccw(c5563.65,6660.35) 5592,6660.35 ; 5591,7081 5592,7080 5592,6946 ; v1@5592,6482 5592,6946 ; 5592,6607.24 cw(c5616.76,6607.24) R94.1@5599.25,6624.75 ; 5592,6662.76 ccw(c5616.76,6662.76) R94.1@5599.25,6645.25 ; R93.1@6030.75,6960.25 ccw(c6005.99,6985.01) 6041,6985.01 ccw(c6076.01,6985.01) R93.1@6051.25,6960.25 ; C53.2@6030.75,7004.75 cw(c6005.99,6979.99) 6041,6979.99 cw(c6076.01,6979.99) C53.2@6051.25,7004.75 ; C53.2@6030.75,7025.25 ccw(c6005.99,7050.01) 6041,7050.01 ccw(c6076.01,7050.01) C53.2@6051.25,7025.25 ; C52.1@6030.75,7069.75 cw(c6005.99,7044.99) 6041,7044.99 cw(c6076.01,7044.99) C52.1@6051.25,7069.75 ; R93.1@6035.7,6955.3 ccw(c6022.89,6968.11) 6041,6968.11 ccw(c6059.11,6968.11) R93.1@6046.3,6955.3 ; C53.2@6035.7,7009.7 cw(c6022.89,6996.89) 6041,6996.89 cw(c6059.11,6996.89) C53.2@6046.3,7009.7 ; C53.2@6035.7,7020.3 ccw(c6022.89,7033.11) 6041,7033.11 ccw(c6059.11,7033.11) C53.2@6046.3,7020.3 ; C52.1@6035.7,7074.7 cw(c6022.89,7061.89) 6041,7061.89 cw(c6059.11,7061.89) C52.1@6046.3,7074.7 ; R93.1@6041,6950 C53.2@6041,7015 C52.1@6041,7080
  Bottom Layer w10: R96.2@5455,7081 5591,7081 ; R96.2@5464.19,7071.81 cw(c5486.38,7049.62) 5486.38,7081 cw(c5486.38,7112.38) R96.2@5464.19,7090.19 ; 5750,7130 v3(5750,7240) ; 5751,7127 5751,6903 5760.85,6893.15 5893,6893.15 ; v1@5896.15,7093 5896.15,6896.3 5893,6893.15 ; 6010.69,6925.69 cw(c6038,6898.37) R93.1@6038,6937 ; 6017.93,6932.93 ccw(c6000.86,6950) R93.1@6025,6950 ; R93.1@6035,6950 5978.15,6893.15 5893,6893.15
  Bottom Layer w15: C2.2@2848.06,5828.94 ccw(c2813.22,5863.78) 2862.5,5863.78 ; C1.2@2849.06,5885.06 cw(c2816.63,5852.63) 2862.5,5852.63 cw(c2908.37,5852.63) C1.2@2875.94,5885.06 ; C1.2@2849.06,5914.94 ccw(c2816.63,5947.37) 2862.5,5947.37 ccw(c2908.37,5947.37) C1.2@2875.94,5914.94 ; C2.2@2861.5,5814 2862.5,5815 C1.2@2862.5,5900 2862.5,5965 CE2.2@2882.5,5985 ; 2862.5,5858.96 ccw(c2904.96,5858.96) C2.2@2874.94,5828.94 ; C1.2@2862.5,5906.54 cw(c2955.96,5906.54) CE2.2@2889.87,5972.63 ; 2862.5,5942.75 cw(c2919.75,5942.75) CE2.2@2879.27,5983.23 ; L1.2@3021.89,6480.61 ccw(c3002.32,6500.18) 3030,6500.18 ; C33.2@3022.58,6532.58 cw(c3004.65,6514.65) 3030,6514.65 cw(c3055.35,6514.65) C33.2@3037.42,6532.58 ; C33.2@3022.58,6547.42 ccw(c3004.65,6565.35) 3030,6565.35 ccw(c3055.35,6565.35) C33.2@3037.42,6547.42 ; C34.2@3022.58,6597.58 cw(c3004.65,6579.65) 3030,6579.65 cw(c3055.35,6579.65) C34.2@3037.42,6597.58 ; C34.2@3022.58,6612.42 ccw(c3004.65,6630.35) 3030,6630.35 ccw(c3055.35,6630.35) C34.2@3037.42,6612.42 ; C29.2@3022.58,6662.58 cw(c3004.65,6644.65) 3030,6644.65 cw(c3055.35,6644.65) C29.2@3037.42,6662.58 ; 3030,6512.25 ccw(c3074.75,6512.25) L1.2@3043.11,6480.61 ; C29.2@3030,6670 C34.2@3030,6605 C33.2@3030,6540 3030,6473 L1.2@3033,6470 ; 3329,6748 3329,6769 ; v1(4253,6238) 4253,6235 4251,6233 4523,6233 4523,6150 4523,6125 4529,6119 C32.2@4555,6119 ; 4389,7681 4566,7504 R40.2@4604,7504 R39.2@4669,7504 R38.2@4734,7504 R37.2@4799,7504 R36.2@4864,7504 R35.2@4929,7504 R34.2@4994,7504 R33.2@5059,7504 R32.2@5124,7504 ; C32.2@4547.58,6111.58 ccw(c4529.65,6093.65) 4529.65,6119 ccw(c4529.65,6144.35) C32.2@4547.58,6126.42 ; R40.2@4596.58,7496.58 ccw(c4578.65,7478.65) 4578.65,7504 ccw(c4578.65,7529.35) R40.2@4596.58,7511.42 ; R40.2@4611.42,7496.58 cw(c4629.35,7478.65) 4629.35,7504 cw(c4629.35,7529.35) R40.2@4611.42,7511.42 ; R39.2@4661.58,7496.58 ccw(c4643.65,7478.65) 4643.65,7504 ccw(c4643.65,7529.35) R39.2@4661.58,7511.42 ; R39.2@4676.42,7496.58 cw(c4694.35,7478.65) 4694.35,7504 cw(c4694.35,7529.35) R39.2@4676.42,7511.42 ; R38.2@4726.58,7496.58 ccw(c4708.65,7478.65) 4708.65,7504 ccw(c4708.65,7529.35) R38.2@4726.58,7511.42 ; R38.2@4741.42,7496.58 cw(c4759.35,7478.65) 4759.35,7504 cw(c4759.35,7529.35) R38.2@4741.42,7511.42 ; R37.2@4791.58,7496.58 ccw(c4773.65,7478.65) 4773.65,7504 ccw(c4773.65,7529.35) R37.2@4791.58,7511.42 ; R37.2@4806.42,7496.58 cw(c4824.35,7478.65) 4824.35,7504 cw(c4824.35,7529.35) R37.2@4806.42,7511.42 ; R36.2@4856.58,7496.58 ccw(c4838.65,7478.65) 4838.65,7504 ccw(c4838.65,7529.35) R36.2@4856.58,7511.42 ; R36.2@4871.42,7496.58 cw(c4889.35,7478.65) 4889.35,7504 cw(c4889.35,7529.35) R36.2@4871.42,7511.42 ; R35.2@4921.58,7496.58 ccw(c4903.65,7478.65) 4903.65,7504 ccw(c4903.65,7529.35) R35.2@4921.58,7511.42 ; R35.2@4936.42,7496.58 cw(c4954.35,7478.65) 4954.35,7504 cw(c4954.35,7529.35) R35.2@4936.42,7511.42 ; R34.2@4986.58,7496.58 ccw(c4968.65,7478.65) 4968.65,7504 ccw(c4968.65,7529.35) R34.2@4986.58,7511.42 ; R34.2@5001.42,7496.58 cw(c5019.35,7478.65) 5019.35,7504 cw(c5019.35,7529.35) R34.2@5001.42,7511.42 ; R33.2@5051.58,7496.58 ccw(c5033.65,7478.65) 5033.65,7504 ccw(c5033.65,7529.35) R33.2@5051.58,7511.42 ; R33.2@5066.42,7496.58 cw(c5084.35,7478.65) 5084.35,7504 cw(c5084.35,7529.35) R33.2@5066.42,7511.42 ; R32.2@5116.58,7496.58 ccw(c5098.65,7478.65) 5098.65,7504 ccw(c5098.65,7529.35) R32.2@5116.58,7511.42 ; R32.2@5120.45,7491.12 cw(c5110.99,7464.75) v1@5139,7464.75 ; R32.2@5125.52,7505.24 cw(c5118.64,7486.07) 5139,7486.07 ; R32.2@5131.42,7496.58 cw(c5149.35,7478.65) 5149.35,7504 cw(c5149.35,7529.35) R32.2@5131.42,7511.42 ; v1(5139,7468) 5139,7489 R32.2@5124,7504 ; R31.2@5181.58,7496.58 ccw(c5163.65,7478.65) 5163.65,7504 ccw(c5163.65,7529.35) R31.2@5181.58,7511.42 ; R31.2@5196.42,7496.58 cw(c5214.35,7478.65) 5214.35,7504 cw(c5214.35,7529.35) R31.2@5196.42,7511.42 ; R30.2@5246.58,7496.58 ccw(c5228.65,7478.65) 5228.65,7504 ccw(c5228.65,7529.35) R30.2@5246.58,7511.42 ; R30.2@5261.42,7496.58 cw(c5279.35,7478.65) 5279.35,7504 cw(c5279.35,7529.35) R30.2@5261.42,7511.42 ; R59.2@5270,5702.5 cw(c5270,5669.91) 5293.05,5692.95 ; R59.2@5270,5716 5296,5690 U2.9@5400,5690 ; R59.2@5280.5,5713 ccw(c5298.61,5713) 5285.8,5700.2 ; R29.2@5311.58,7496.58 ccw(c5293.65,7478.65) 5293.65,7504 ccw(c5293.65,7529.35) R29.2@5311.58,7511.42 ; R29.2@5326.42,7496.58 cw(c5344.35,7478.65) 5344.35,7504 cw(c5344.35,7529.35) R29.2@5326.42,7511.42 ; R28.2@5376.58,7493.58 cw(c5358.65,7475.65) 5384,7475.65 cw(c5409.35,7475.65) R28.2@5391.42,7493.58 ; R28.2@5376.58,7496.58 ccw(c5358.65,7478.65) 5358.65,7504 ccw(c5358.65,7529.35) R28.2@5376.58,7511.42 ; v1(5384,7320.77) R28.2@5384,7504 ; U2.9@5385.86,5675.86 ccw(c5351.72,5641.72) 5351.72,5690 ccw(c5351.72,5738.28) U2.9@5385.86,5704.14 ; R28.2@5391.42,7496.58 cw(c5409.35,7478.65) 5409.35,7504 cw(c5409.35,7529.35) R28.2@5391.42,7511.42 ; R27.2@5441.58,7496.58 ccw(c5423.65,7478.65) 5423.65,7504 ccw(c5423.65,7529.35) R27.2@5441.58,7511.42 ; R27.2@5456.42,7496.58 cw(c5474.35,7478.65) 5474.35,7504 cw(c5474.35,7529.35) R27.2@5456.42,7511.42 ; R26.2@5506.58,7496.58 ccw(c5488.65,7478.65) 5488.65,7504 ccw(c5488.65,7529.35) R26.2@5506.58,7511.42 ; R26.2@5521.42,7496.58 cw(c5539.35,7478.65) 5539.35,7504 cw(c5539.35,7529.35) R26.2@5521.42,7511.42 ; C25.2@5535,5652.5 5668.5,5652.5 C22.1@5675,5659 ; C25.2@5549.94,5639.06 cw(c5582.37,5606.63) 5582.37,5652.5 cw(c5582.37,5698.37) C25.2@5549.94,5665.94 ; R25.2@5571.58,7496.58 ccw(c5553.65,7478.65) 5553.65,7504 ccw(c5553.65,7529.35) R25.2@5571.58,7511.42 ; 5576.2,5652.5 ccw(c5576.2,5689.8) C23.2@5602.58,5663.42 ; R25.2@5586.42,7496.58 cw(c5604.35,7478.65) 5604.35,7504 cw(c5604.35,7529.35) R25.2@5586.42,7511.42 ; v1(5616,7507) 5613,7504 R25.2@5579,7504 R26.2@5514,7504 R27.2@5449,7504 R28.2@5384,7504 ; C23.2@5617.42,5663.42 ccw(c5643.8,5689.8) 5643.8,5652.5 ; 5641.2,5652.5 ccw(c5641.2,5689.8) C22.1@5667.58,5663.42 ; R32.2@5124,7504 R31.2@5189,7504 R30.2@5254,7504 R29.2@5319,7504 R28.2@5384,7504
  other v1: 5284,5495 2899,5877 4081,6166 3695,6185 3485,6236 3121,6240 3631,6243 5016,6619 3958,6830 3275,7023 3503,7085 5899,7094 3586,7481 4186,7599 3764,7601 4073,7712 4621,7756 4748,7756 5442,7756 5576,7758 4689,7759 4807,7759 5125,7759 5381,7759 4865,7760 4995,7760 5191,7760 5256,7760 4930,7761 5060,7761
  other v2: 3592,5380 5810,5424 3321,5492 5673,5542 3678,5569 2295,5615 5642,5679 3184,5711 4941,5722 3269,5728 3927,5747 4192,5764 3232,5775 4105,5778 5974,5805 3052,5812 5651,5914 2452,5962 4469,6023 4337,6156 5011,6202 2513,6210 4086,6236 5826,6263 2980,6275 3582,6287 5985,6316 4840,6363 4483,6366 3906,6379 5244,6456 4943,6478 4865,6541 3979,6563 5044,6591 5556,6598 4193,6619 5722,6635 4322,6660 5979,6673 5202,6693 5255,6695 5201,6757 5252,6759 5057,6774 5530,6788 4491,6824 5498,6835 3006,6880 6031,6896 2804,6989 4717,6989 2444,6995 3352,7011 4544,7044 2698,7111 4637,7152 2895,7172 2599,7227 5925,7303 4879,7320 5658,7342 5541,7471 4872,7476 6036,7534 3020,7608 2702,7620 3501,7648 2328,7727 4392,7759 3584,7936 5679,7944 3377,7979
EMMC_RSTN: J2.18
EXT_RESETN: J1.75 J4.5 RESET.1 | length 3918.7
  Top Layer w6.5: 3800.46,5400.88 ccw(c3827.88,5428.3) J4.5@3833.98,5390.01 ; 3804.37,5396.98 cw(c3776.31,5368.92) J4.5@3815.99,5368.92 ; 3809.47,5391.87 ccw(c3830.36,5412.76) J4.5@3835.01,5383.59 ; 3815.46,5385.88 cw(c3798.5,5368.92) J4.5@3822.49,5368.92 ; J4.5@3837.35,5364 3798,5403.35 3798,5473 3752,5519 3752,5758 3872,5878 3898.77,5878 3909.68,5888.92 3909.68,6171.03 3945.66,6207 4471,6207 4487.75,6223.75 4849.25,6223.75 4909.68,6163.32 4909.68,6045.32 4934,6021.01 J1.75@4934,5947 ; J1.75@4926,5991.62 ccw(c4906.68,6010.94) 4934,6010.94 ccw(c4961.32,6010.94) J1.75@4942,5991.62
  Bottom Layer w6.5: RESET.1@2717,5422.5 2717,5441 2738,5462 ; RESET.1@2717.32,5420.94 cw(c2733.79,5430.71) 2720.25,5444.25 ; RESET.1@2722.91,5424.25 cw(c2741.22,5435.11) 2726.16,5450.16 ; RESET.1@2728.5,5427.57 cw(c2748.64,5439.52) 2732.08,5456.08 ; RESET.1@2734.09,5430.88 cw(c2756.07,5443.92) 2738,5462 ; 3800.46,5400.88 ccw(c3827.88,5428.3) J4.5@3833.98,5390.01 ; 3804.37,5396.98 cw(c3776.31,5368.92) J4.5@3815.99,5368.92 ; 3809.47,5391.87 ccw(c3830.36,5412.76) J4.5@3835.01,5383.59 ; 3815.46,5385.88 cw(c3798.5,5368.92) J4.5@3822.49,5368.92 ; J4.5@3837.35,5369.11 J4.5@3837.35,5364 3798,5403.35 3798,5473 3782,5489 3652,5489 3641.28,5478.28 3641.28,5429.28 3617.25,5405.25 2950.75,5405.25 2894,5462 2738,5462
EXT_WAKEUP: J1.78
